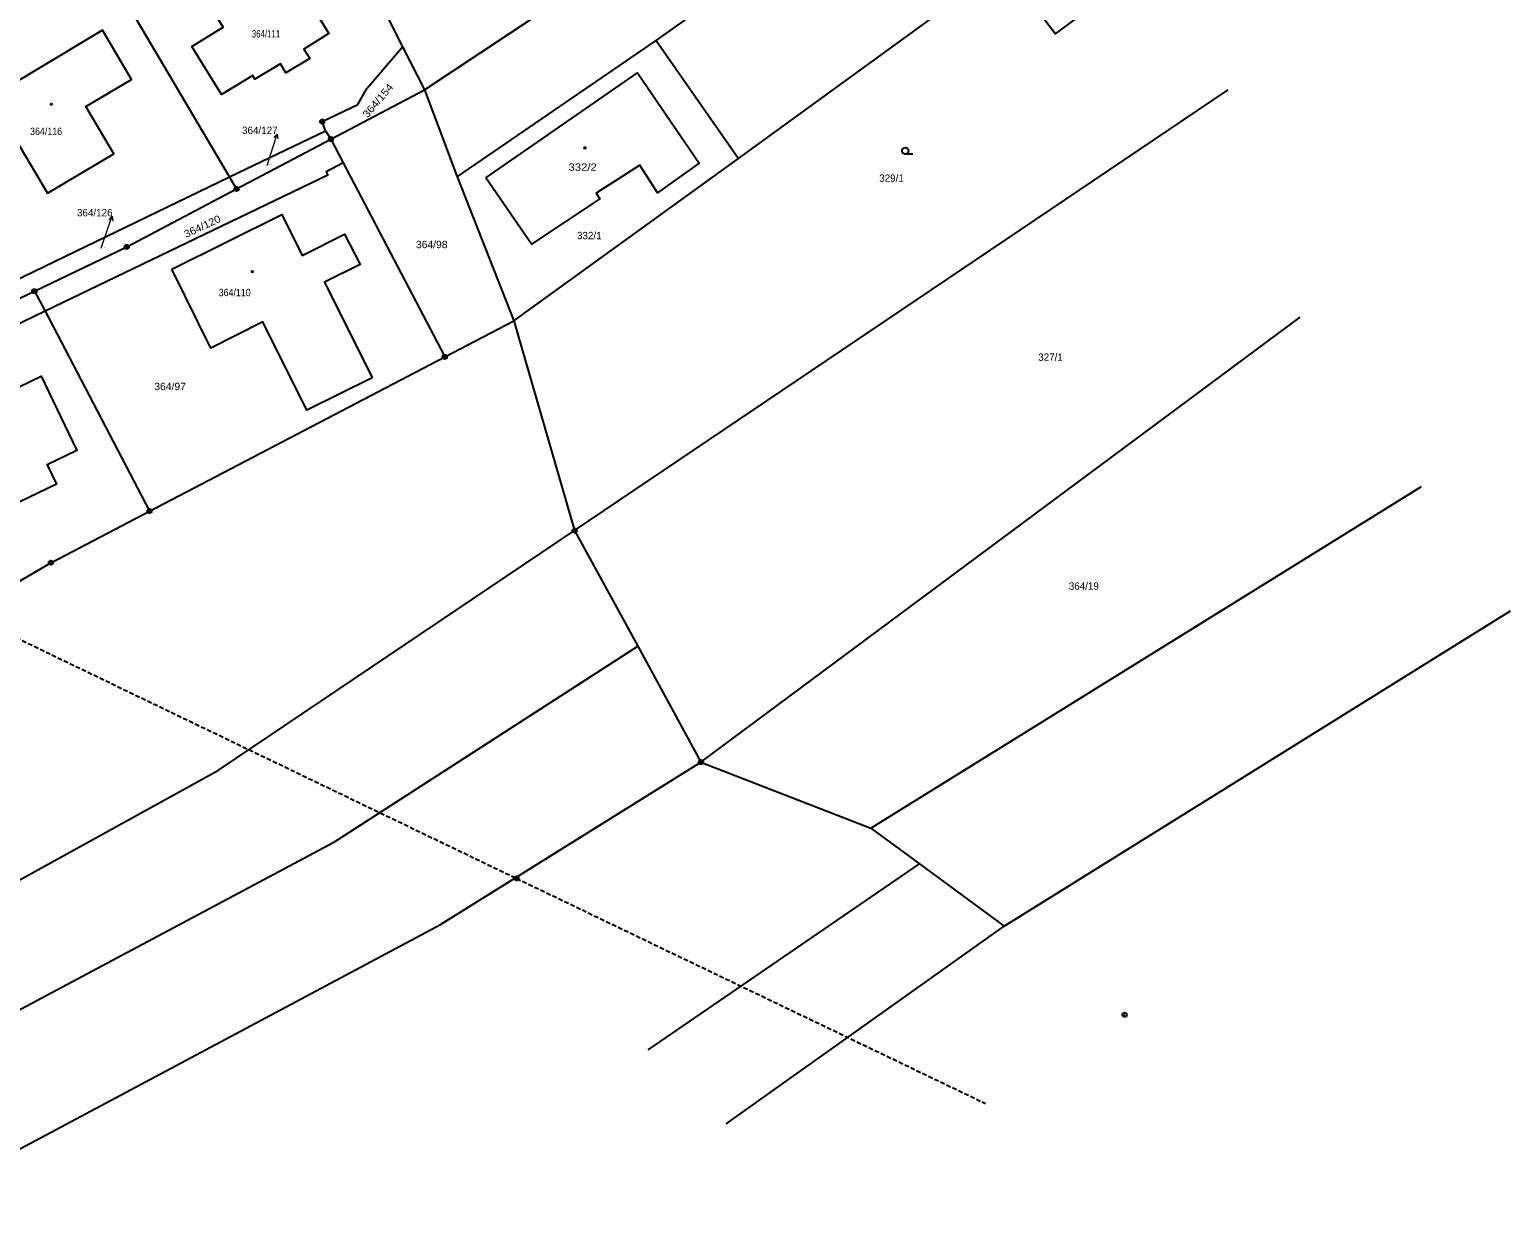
# Model space of a CAD drawing. Extents: x -592965 to -592390, y -1145071 to -1144631.
# Drawn here: x -592594.1 to -592423, y -1145063.9 to -1144927.6 of the extents above; entities that cross this region are included whole.
import ezdxf

# ---------------------------------------------------------------- set-up
doc = ezdxf.new("R2010")
doc.units = 0
doc.header["$LTSCALE"] = 0.17
doc.linetypes.add('MEDIUM_DASHED', pattern=[4.5, 3, -1.5])
doc.layers.add('4', color=7, linetype='Continuous', lineweight=25)

msp = doc.modelspace()

# ---------------------------------------------------------------- linework, layer by layer
at = {"layer": '4'}
for p, q in [((-592548.47, -1144934.53), (-592502.43, -1144904)), ((-592521.69, -1144928.84), (-592497.22, -1144911.4)), ((-592544.67, -1144944.59), (-592521.69, -1144928.84)), ((-592521.69, -1144928.84), (-592512.18, -1144942.45)), ((-592559.26, -1144940.23), (-592548.47, -1144934.53)), ((-592548.47, -1144934.53), (-592544.67, -1144944.59)), ((-592531.12, -1144985.47), (-592455.63, -1144934.53)), ((-592559.91, -1144939.25), (-592559.26, -1144940.23)), ((-592538.13, -1144961.22), (-592512.18, -1144942.45)), ((-592492.045, -1144941.96), (-592492.92, -1144941.96)), ((-592544.67, -1144944.59), (-592538.13, -1144961.22)), ((-592593.51, -1144957.8), (-592582.85, -1144952.69)), ((-592596.1, -1144959.04), (-592593.51, -1144957.8)), ((-592538.13, -1144961.22), (-592531.12, -1144985.47)), ((-592516.52, -1145012.22), (-592447.31, -1144960.8)), ((-592496.89, -1145019.85), (-592433.29, -1144980.38)), ((-592591.61, -1144989.18), (-592580.21, -1144983.22)), ((-592572.24, -1145013.15), (-592531.12, -1144985.47)), ((-592611.32, -1145000.71), (-592591.61, -1144989.18)), ((-592481.51, -1145031.18), (-592423.02, -1144994.73)), ((-592558.85, -1145021.44), (-592523.82, -1144998.85)), ((-592546.61, -1145030.99), (-592516.52, -1145012.22)), ((-592516.52, -1145012.22), (-592496.89, -1145019.85)), ((-592496.89, -1145019.85), (-592491.26, -1145024)), ((-592608.34, -1145047.82), (-592558.85, -1145021.44)), ((-592522.63, -1145045.49), (-592491.26, -1145024)), ((-592491.26, -1145024), (-592481.51, -1145031.18)), ((-592608.36, -1145063.93), (-592546.61, -1145030.99)), ((-592513.61, -1145054.05), (-592481.51, -1145031.18))]:
    msp.add_line(p, q, dxfattribs=at)
for points in [[(-592512.18, -1144942.45), (-592481.52, -1144920.17), (-592475.56, -1144928.06), (-592458.12, -1144915.16), (-592458.74, -1144914.34), (-592458, -1144913.8)], [(-592570.16, -1144945.99), (-592570.98, -1144944.6), (-592588.13, -1144915.55)], [(-592554.39, -1144922.78), (-592550.98, -1144929.55), (-592548.47, -1144934.53)], [(-592559.91, -1144939.25), (-592560.27, -1144938.2), (-592556.15, -1144936.22), (-592555.13, -1144934.37), (-592550.98, -1144929.55)], [(-592637.49, -1144944.42), (-592626.62, -1144966.7), (-592626.18, -1144967.53), (-592625.48, -1144968.32), (-592624.23, -1144969.12), (-592622.8, -1144969.4), (-592621.85, -1144969.17), (-592597.16, -1144957.25), (-592570.98, -1144944.6), (-592559.91, -1144939.25)], [(-592582.85, -1144952.69), (-592570.16, -1144945.99), (-592559.26, -1144940.23)], [(-592559.26, -1144940.23), (-592557.84, -1144942.95), (-592546.11, -1144965.39)], [(-592557.84, -1144942.95), (-592559.8, -1144944.02), (-592559.63, -1144944.38), (-592592.29, -1144960.13), (-592621.67, -1144974.31), (-592621.74, -1144974.77), (-592622.49, -1144975.13), (-592624.43, -1144976.07)], [(-592593.51, -1144957.8), (-592592.29, -1144960.13), (-592580.21, -1144983.22)], [(-592580.21, -1144983.22), (-592546.11, -1144965.39), (-592538.13, -1144961.22)], [(-592531.12, -1144985.47), (-592523.82, -1144998.85), (-592516.52, -1145012.22)], [(-592639.04, -1145048.25), (-592609.13, -1145033.5), (-592572.24, -1145013.15)]]:
    msp.add_lwpolyline(points, dxfattribs=at)
for points in [[(-592565.26, -1144918.66), (-592559.51, -1144928.03), (-592562.38, -1144929.81), (-592561.72, -1144930.89), (-592564.47, -1144932.57), (-592565.11, -1144931.52), (-592568.04, -1144933.29), (-592568.3, -1144932.86), (-592571.92, -1144935.08), (-592575.33, -1144929.51), (-592571.71, -1144927.3), (-592573.79, -1144923.9)], [(-592601.13, -1144936.9), (-592597.88, -1144942.39), (-592595.3, -1144940.9), (-592592.02, -1144946.46), (-592584.34, -1144941.94), (-592587.57, -1144936.44), (-592582.29, -1144933.34), (-592585.64, -1144927.65)], [(-592541.39, -1144944.69), (-592523.86, -1144932.58), (-592516.74, -1144943), (-592521.55, -1144946.44), (-592523.59, -1144943.25), (-592528.63, -1144946.49), (-592528.22, -1144947.12), (-592536.09, -1144952.38)], [(-592577.64, -1144955.27), (-592564.93, -1144948.92), (-592562.58, -1144953.68), (-592557.68, -1144951.23), (-592555.9, -1144954.72), (-592560.02, -1144956.76), (-592554.5, -1144967.81), (-592562.04, -1144971.57), (-592567.12, -1144961.36), (-592573.14, -1144964.37)], [(-592601.78, -1144983.1), (-592604.44, -1144977.55), (-592603.32, -1144977.01), (-592605.06, -1144973.35), (-592601, -1144971.39), (-592600.86, -1144971.68), (-592596.51, -1144969.57), (-592596.55, -1144969.48), (-592592.72, -1144967.63), (-592588.6, -1144976.22), (-592592.06, -1144977.86), (-592590.98, -1144980.12), (-592596.32, -1144982.68), (-592596.19, -1144982.99), (-592599.54, -1144984.65), (-592600.66, -1144982.55)]]:
    msp.add_lwpolyline(points, close=True, dxfattribs=at)
at = {"layer": '4', "lineweight": 13}
for points in [[(-592566.64, -1144943.29), (-592565.939, -1144941.07), (-592565.487, -1144939.64)], [(-592565.876, -1144940.041), (-592565.487, -1144939.64), (-592565.4, -1144940.192)], [(-592585.82, -1144952.82), (-592585.021, -1144950.564), (-592584.52, -1144949.15)], [(-592584.923, -1144949.538), (-592584.52, -1144949.15), (-592584.451, -1144949.705)]]:
    msp.add_lwpolyline(points, dxfattribs=at)
at = {"layer": '4', "linetype": 'MEDIUM_DASHED'}
msp.add_lwpolyline([(-592669.72, -1144961.82), (-592599.07, -1144996.19), (-592537.81, -1145025.68), (-592483.65, -1145051.69)], dxfattribs=at)
at = {"layer": '4'}
for centre, radius in [((-592591.56, -1144936.21), 0.0875), ((-592560.27, -1144938.2), 0.25), ((-592560.27, -1144938.2), 0.0164), ((-592559.26, -1144940.23), 0.25), ((-592559.26, -1144940.23), 0.0164), ((-592529.93, -1144941.23), 0.0875), ((-592492.92, -1144941.585), 0.375), ((-592570.16, -1144945.99), 0.25), ((-592570.16, -1144945.99), 0.0164), ((-592582.85, -1144952.69), 0.25), ((-592582.85, -1144952.69), 0.0164), ((-592568.35, -1144955.55), 0.0875), ((-592593.51, -1144957.8), 0.25), ((-592593.51, -1144957.8), 0.0164), ((-592546.11, -1144965.39), 0.25), ((-592546.11, -1144965.39), 0.0164), ((-592580.21, -1144983.22), 0.25), ((-592580.21, -1144983.22), 0.0164), ((-592531.12, -1144985.47), 0.25), ((-592531.12, -1144985.47), 0.0164), ((-592591.61, -1144989.18), 0.25), ((-592591.61, -1144989.18), 0.0164), ((-592516.52, -1145012.22), 0.25), ((-592516.52, -1145012.22), 0.0164), ((-592537.81, -1145025.68), 0.25), ((-592537.81, -1145025.68), 0.15), ((-592537.81, -1145025.68), 0.075), ((-592467.59, -1145041.44), 0.25), ((-592467.59, -1145041.44), 0.0164)]:
    msp.add_circle(centre, radius, dxfattribs=at)

# ---------------------------------------------------------------- texts
for s, height, width, p in [('364/111', 0.85, 0.8, (-592568.411, -1144928.48)), ('364/116', 0.85, 0.9, (-592594.014, -1144939.75)), ('364/127', 0.1, 1.1, (-592566.64, -1144943.29)), ('332/2', 0.85, 1.15, (-592531.826, -1144943.885)), ('364/98', 0.85, 1.05, (-592549.446, -1144952.83)), ('364/126', 0.1, 1.1, (-592585.82, -1144952.82)), ('364/110', 0.85, 0.9, (-592572.23, -1144958.38)), ('364/97', 0.85, 1.05, (-592579.669, -1144969.24))]:
    msp.add_text(s, height=height, dxfattribs=dict(at, width=width)).set_placement(p)
for s, rotation, width, p in [('364/154', 49.638, 1.15, (-592555.05, -1144937.85)), ('364/120', 25.2, 1.1, (-592575.987, -1144951.654))]:
    msp.add_text(s, height=0.85, rotation=rotation, dxfattribs=dict(at, width=width)).set_placement(p)
for s, p in [('364/127', (-592569.532, -1144939.64)), ('329/1', (-592495.93, -1144945.16)), ('364/126', (-592588.6, -1144949.15)), ('332/1', (-592530.84, -1144951.795)), ('327/1', (-592477.564, -1144965.85)), ('364/19', (-592474.03, -1144992.31))]:
    msp.add_text(s, height=0.85, dxfattribs=at).set_placement(p)

doc.saveas('drawing.dxf')
